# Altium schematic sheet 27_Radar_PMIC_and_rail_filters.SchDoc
size 289 x 400 mm
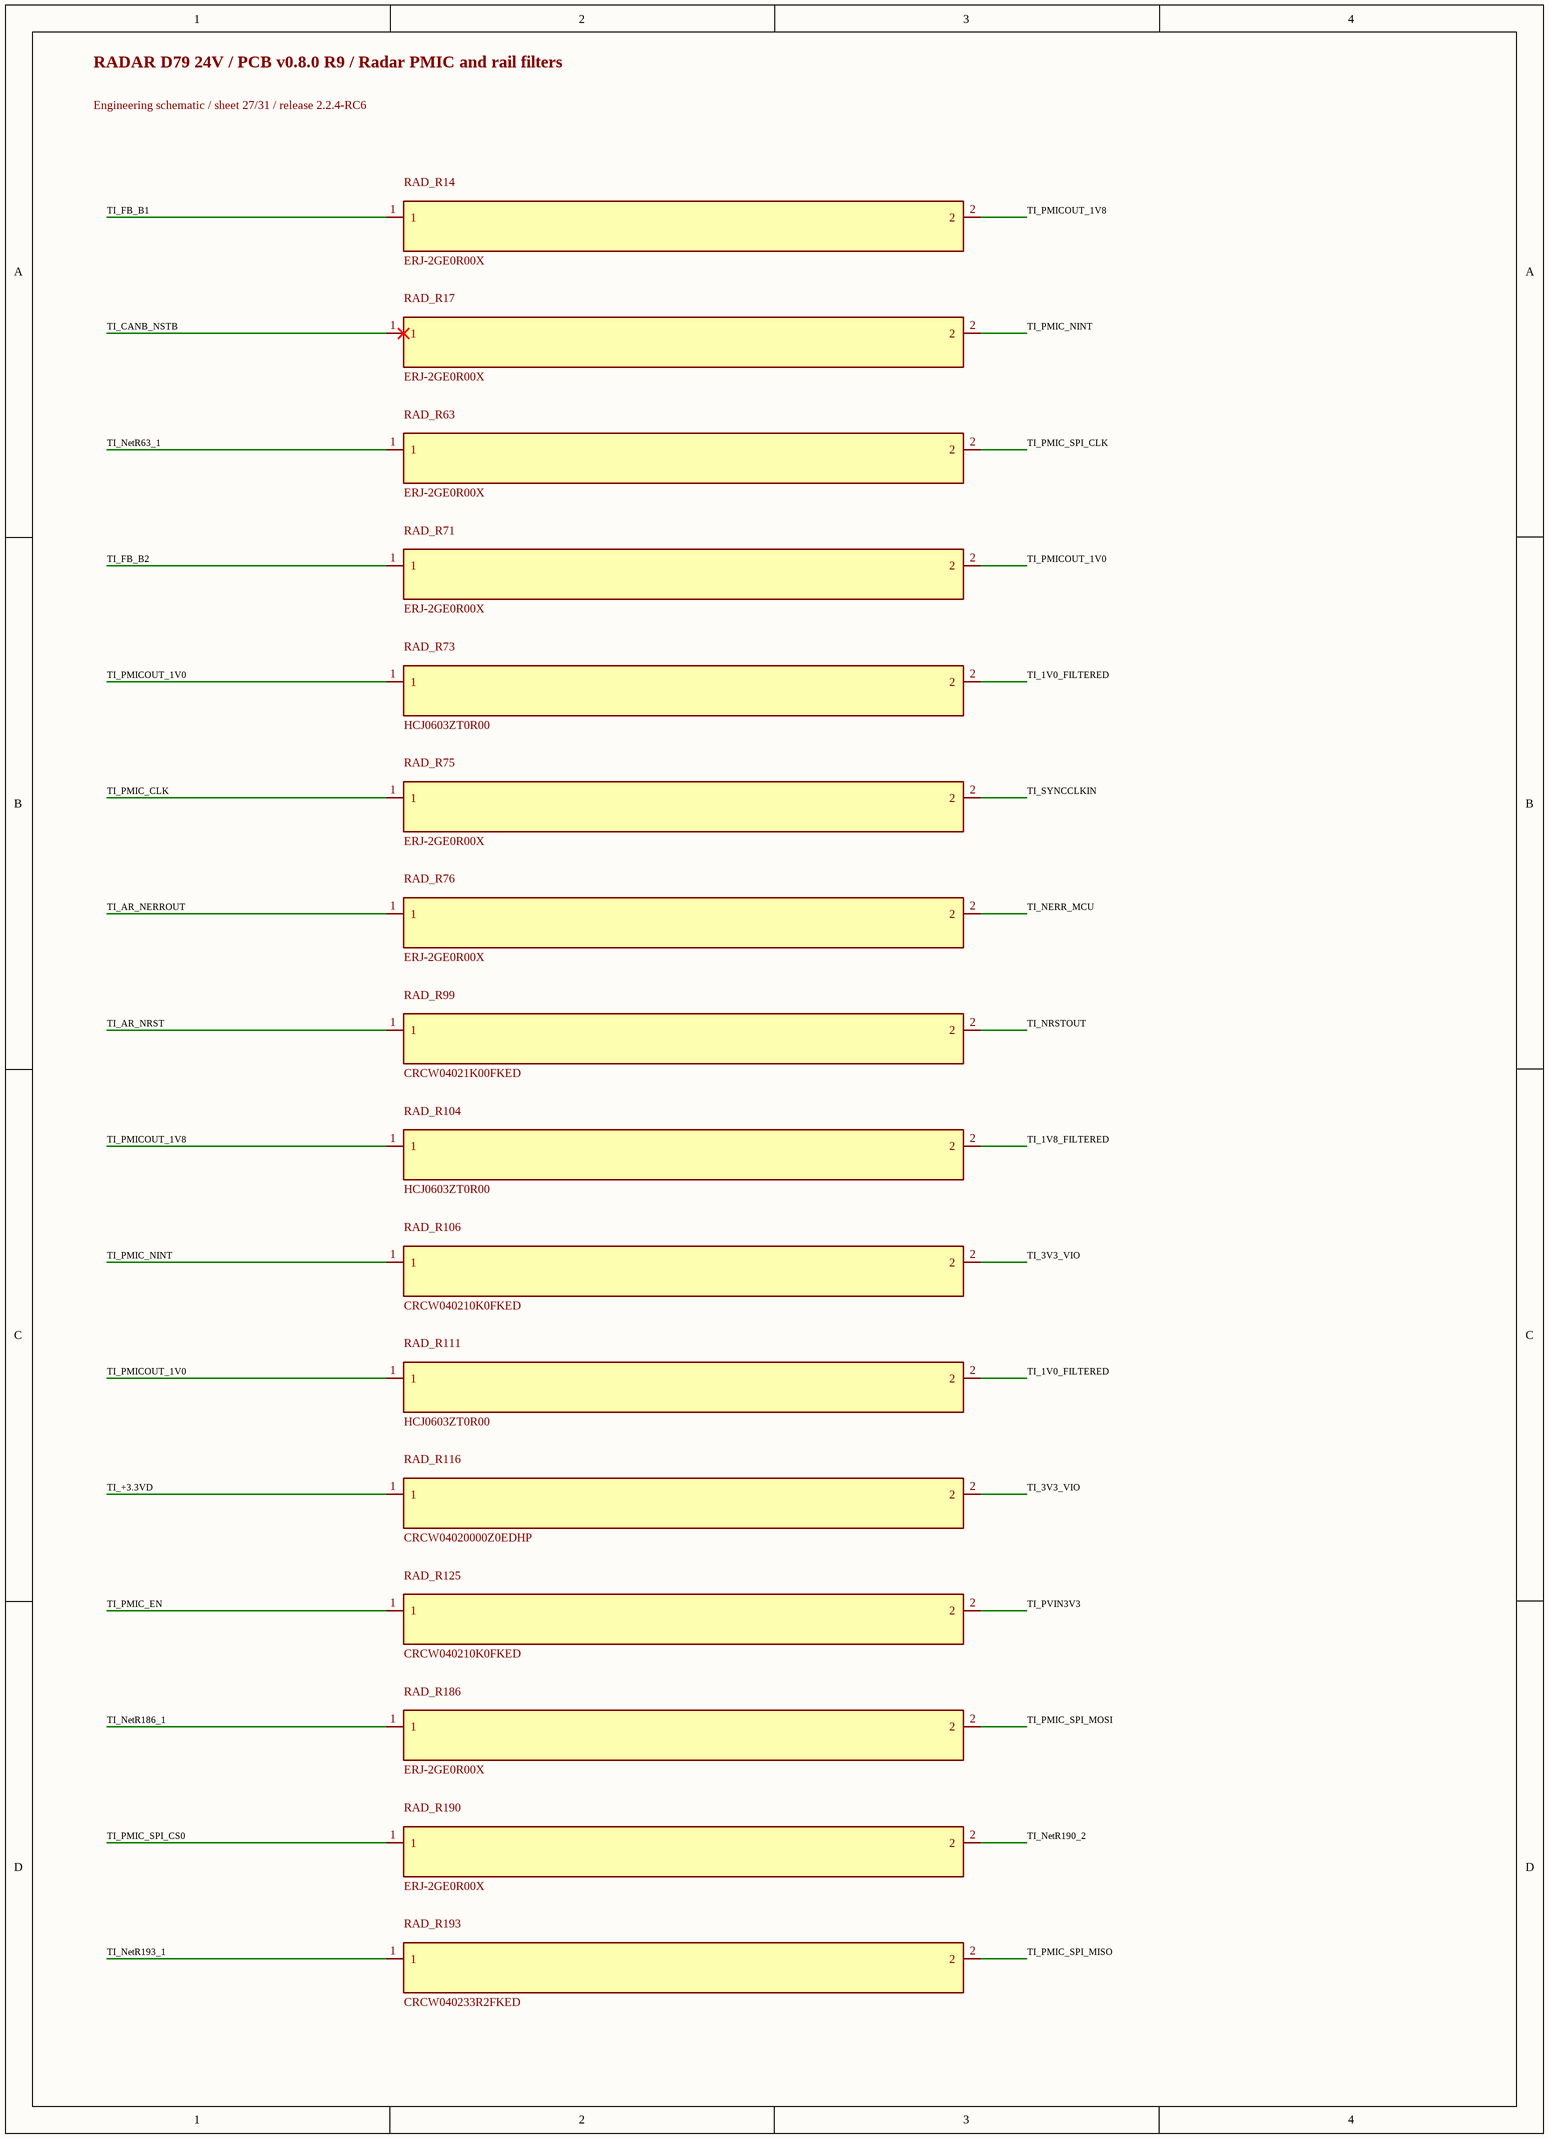
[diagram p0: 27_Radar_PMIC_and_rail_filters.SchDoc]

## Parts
RAD_R14  ERJ-2GE0R00X  [0402L]
RAD_R17  ERJ-2GE0R00X  [0402L]
RAD_R63  ERJ-2GE0R00X  [0402L]
RAD_R71  ERJ-2GE0R00X  [0402L]
RAD_R73  HCJ0603ZT0R00  [FP-HCJ0603ZT0R00_0603-MFG]
RAD_R75  ERJ-2GE0R00X  [0402L]
RAD_R76  ERJ-2GE0R00X  [0402L]
RAD_R99  CRCW04021K00FKED  [0402L]
RAD_R104  HCJ0603ZT0R00  [FP-HCJ0603ZT0R00_0603-MFG]
RAD_R106  CRCW040210K0FKED  [0402L]
RAD_R111  HCJ0603ZT0R00  [FP-HCJ0603ZT0R00_0603-MFG]
RAD_R116  CRCW04020000Z0EDHP  [0402L]
RAD_R125  CRCW040210K0FKED  [0402L]
RAD_R186  ERJ-2GE0R00X  [0402L]
RAD_R190  ERJ-2GE0R00X  [0402L]
RAD_R193  CRCW040233R2FKED  [0402L]

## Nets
TI_1V0_FILTERED: RAD_R73.2 RAD_R111.2
TI_1V8_FILTERED: RAD_R104.2
TI_3V3_VIO: RAD_R106.2 RAD_R116.2
TI_+3.3VD: RAD_R116.1
TI_AR_NERROUT: RAD_R76.1
TI_AR_NRST: RAD_R99.1
TI_CANB_NSTB: RAD_R17.1
TI_FB_B1: RAD_R14.1
TI_FB_B2: RAD_R71.1
TI_NERR_MCU: RAD_R76.2
TI_NetR63_1: RAD_R63.1
TI_NetR186_1: RAD_R186.1
TI_NetR190_2: RAD_R190.2
TI_NetR193_1: RAD_R193.1
TI_NRSTOUT: RAD_R99.2
TI_PMIC_CLK: RAD_R75.1
TI_PMIC_EN: RAD_R125.1
TI_PMIC_NINT: RAD_R17.2 RAD_R106.1
TI_PMIC_SPI_CLK: RAD_R63.2
TI_PMIC_SPI_CS0: RAD_R190.1
TI_PMIC_SPI_MISO: RAD_R193.2
TI_PMIC_SPI_MOSI: RAD_R186.2
TI_PMICOUT_1V0: RAD_R71.2 RAD_R73.1 RAD_R111.1
TI_PMICOUT_1V8: RAD_R14.2 RAD_R104.1
TI_PVIN3V3: RAD_R125.2
TI_SYNCCLKIN: RAD_R75.2

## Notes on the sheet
- RADAR D79 24V / PCB v0.8.0 R9 / Radar PMIC and rail filters
- Engineering schematic / sheet 27/31 / release 2.2.4-RC6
